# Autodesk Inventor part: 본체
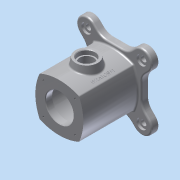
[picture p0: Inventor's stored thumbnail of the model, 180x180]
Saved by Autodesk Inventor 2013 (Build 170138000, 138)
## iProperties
Created: 2016-05
Part Number: 본체
Material: 알루미늄 6061
Document SubType Name: Modeling
Designer: Administrator
Density: 2.71 g/cm^3
Mass: 1111.78 g
Surface Area: 864.18 cm^2
Volume: 410.252 cm^3
Author: Administrator
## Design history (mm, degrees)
sketch "스케치1"
  geometry: L1 (-35.355, -35.355)-(35.355, -35.355); L2 (35.355, -35.355)-(35.355, 35.355); L3 (35.355, 35.355)-(-35.355, 35.355); L4 (-35.355, 35.355)-(-35.355, -35.355); L5 (-35.355, -35.355)-(35.355, 35.355); L6 (35.355, -35.355)-(-35.355, 35.355); L7 (0, 0)-(28.284, 28.284); A1 r 85.579 centre (0, -42.579) between (35.355, 35.355) and (-35.355, 35.355); A2 r 85.579 centre (0, 42.579) between (-35.355, -35.355) and (35.355, -35.355); A3 r 85.579 centre (42.579, 0) between (-35.355, 35.355) and (-35.355, -35.355); A4 r 85.579 centre (-42.579, 0) between (35.355, -35.355) and (35.355, 35.355)
  constraints: 14 end point, 8 point on circle, 4 centre point, 3 equal radius, 2 midpoint, 2 parallel, 2 perpendicular, 1 horizontal, 1 point on line
  dimensions: "d2" = 100 distance of L1.end L3.end; "d75" = 86 dimension on A2 A1
extrude "돌출1" new body sketch "스케치1" distance "d5" = 49; taper "d7" = 0 deg; dims "d6" = 49, "d8" = 0
sketch "스케치2"
  geometry: L1 (0, 0)-(28.284, 28.284); L2 (0, 0)-(24.459, 0); 2 further points
  constraints: 4 end point, 2 coincident, 1 horizontal
  dimensions: "d10" = 40 distance of L1.start L1.end; "d11" = 45 deg angle of L2 L1
hole "구멍1" sketch "스케치2" diameter "d12" = 3.242; stored, may be unused: countersink angle "d16" = 90 deg, drill point angle "d18" = 118 deg; dims "d13" = 7, "d14" = 4, "d15" = 2, "d17" = 10
sketch "스케치3"
  geometry: L1 (-49, -49)-(49, -49); L2 (49, -49)-(49, 49); L3 (49, 49)-(6.849, 49); L4 (-49, 49)-(-49, -49); L5 (-49, -49)-(49, 49); L6 (49, -49)-(-49, 49); L7 (0, 0)-(49.497, 49.497); L8 (6.849, 49)-(-49, 49); L9 (49, 13.189)-(49, 11.235); L10 (36.77, 62.225)-(30.866, 56.322); L11 (62.225, 36.77)-(56.322, 30.866); C1 r 1.621 at (-28.284, 28.284) reference; A1 r 18 centre (49.497, 49.497) between (62.225, 36.77) and (36.77, 62.225); A2 r 85.579 centre (-42.579, 0) between (35.355, -35.355) and (35.355, 35.355) reference; A3 r 85.579 centre (0, 42.579) between (-35.355, -35.355) and (35.355, -35.355) reference; A4 r 85.579 centre (42.579, 0) between (-35.355, 35.355) and (-35.355, -35.355) reference; A5 r 85.579 centre (0, -42.579) between (35.355, 35.355) and (-35.355, 35.355) reference; A6 r 25 centre (13.189, 74) between (13.189, 49) and (30.866, 56.322); A7 r 25 centre (74, 13.189) between (56.322, 30.866) and (49, 13.189); 1 further point
  constraints: 22 end point, 7 parallel, 6 point on circle, 6 tangent, 5 point on line, 3 centre point, 2 coincident, 2 midpoint, 2 perpendicular, 1 equal radius, 1 horizontal
  dimensions: "d22" = 98 distance of L2.end L4.start; "d23" = 98 distance of L2.end L1.end; "d24" = 70 distance of L7.start L7.end; "d26" = 40 distance of L7.start C1.centre (derived); "d40" = 36 diameter of A1; "d129" = 25 radius of A6
extrude "돌출2" join sketch "스케치3" distance "d38" = 12; taper "d39" = 0 deg
extrude "돌출3" join sketch "스케치3" distance "d42" = 12; taper "d43" = 0 deg
sketch "스케치4"
  geometry: L1 (0, 0)-(-28.284, 28.284); L2 (0, 0)-(-11.732, 0); 1 further point
  constraints: 4 end point, 1 coincident, 1 horizontal
  dimensions: "d47" = 40 distance of L1.start L1.end; "d48" = 45 deg angle of L2 L1
hole "구멍3" sketch "스케치4" at (-28.284, 28.284) diameter "d49" = 3.242; stored, may be unused: countersink angle "d53" = 90 deg, drill point angle "d55" = 118 deg; dims "d50" = 7, "d51" = 4, "d52" = 2, "d54" = 10
hole "구멍4" diameter "d61" = 10; stored, may be unused: countersink angle "d65" = 90 deg, drill point angle "d67" = 0 deg; dims "d59" = 10, "d60" = 10, "d62" = 7, "d63" = 18, "d64" = 4, "d66" = 10
node "작업 평면1"
sketch "스케치5"
  geometry: C1 r 20 at (0, 0); 1 further point
  constraints: 1 centre point, 1 coincident
  dimensions: "d72" = 40 diameter of C1
extrude "돌출4" join sketch "스케치5" stored distance "d73" = 12; taper "d74" = 10 deg
hole "구멍7" sketch "스케치2" diameter "d92" = 50; stored, may be unused: countersink angle "d96" = 90 deg, drill point angle "d98" = 0 deg; dims "d93" = 7, "d94" = 70, "d95" = 86, "d97" = 12
hole "구멍8" diameter "d101" = 50; stored, may be unused: countersink angle "d105" = 90 deg, drill point angle "d107" = 0 deg; dims "d99" = 10, "d100" = 10, "d102" = 7, "d103" = 70, "d104" = 86, "d106" = 12
hole "구멍9" diameter "d110" = 25; stored, may be unused: countersink angle "d114" = 90 deg, drill point angle "d116" = 0 deg; dims "d108" = 10, "d109" = 10, "d111" = 7, "d112" = 30, "d113" = 8, "d115" = 12
fillet "모깎기1" dims "d117" = 3
chamfer "모따기1" distance "d118" = 1; stored, may be unused: second distance "d119" = 2, angle "d120" = 45 deg
node "작업 평면2"
sketch "스케치6"
  geometry: L1 (34.285, 49)-(-34.285, 49) reference; 2 further points
  constraints: 1 other
  dimensions: "d121" = 29 distance of point (-29, 0) point (0, 0); "d122" = 49 distance from line of point (-29, 0) L1
feature "엠보싱1" sketch "스케치6" dims "d2" = 100, "d22" = 98, "d23" = 98, "d24" = 70, "d40" = 36, "d75" = 86, "d123" = 0.5, "d124" = 0, "d129" = 25
node "솔리드1"
pattern_circular "원형 패턴1" dims angle "d20" = 360 deg
pattern_circular "원형 패턴3" dims angle "d45" = 360 deg
pattern_circular "원형 패턴4" dims angle "d57" = 360 deg
pattern_circular "원형 패턴5" dims angle "d69" = 360 deg
node "절단 모서리 투영1"
other parameters: "d71" = 55
